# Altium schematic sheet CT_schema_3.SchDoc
size 221 x 258 mm
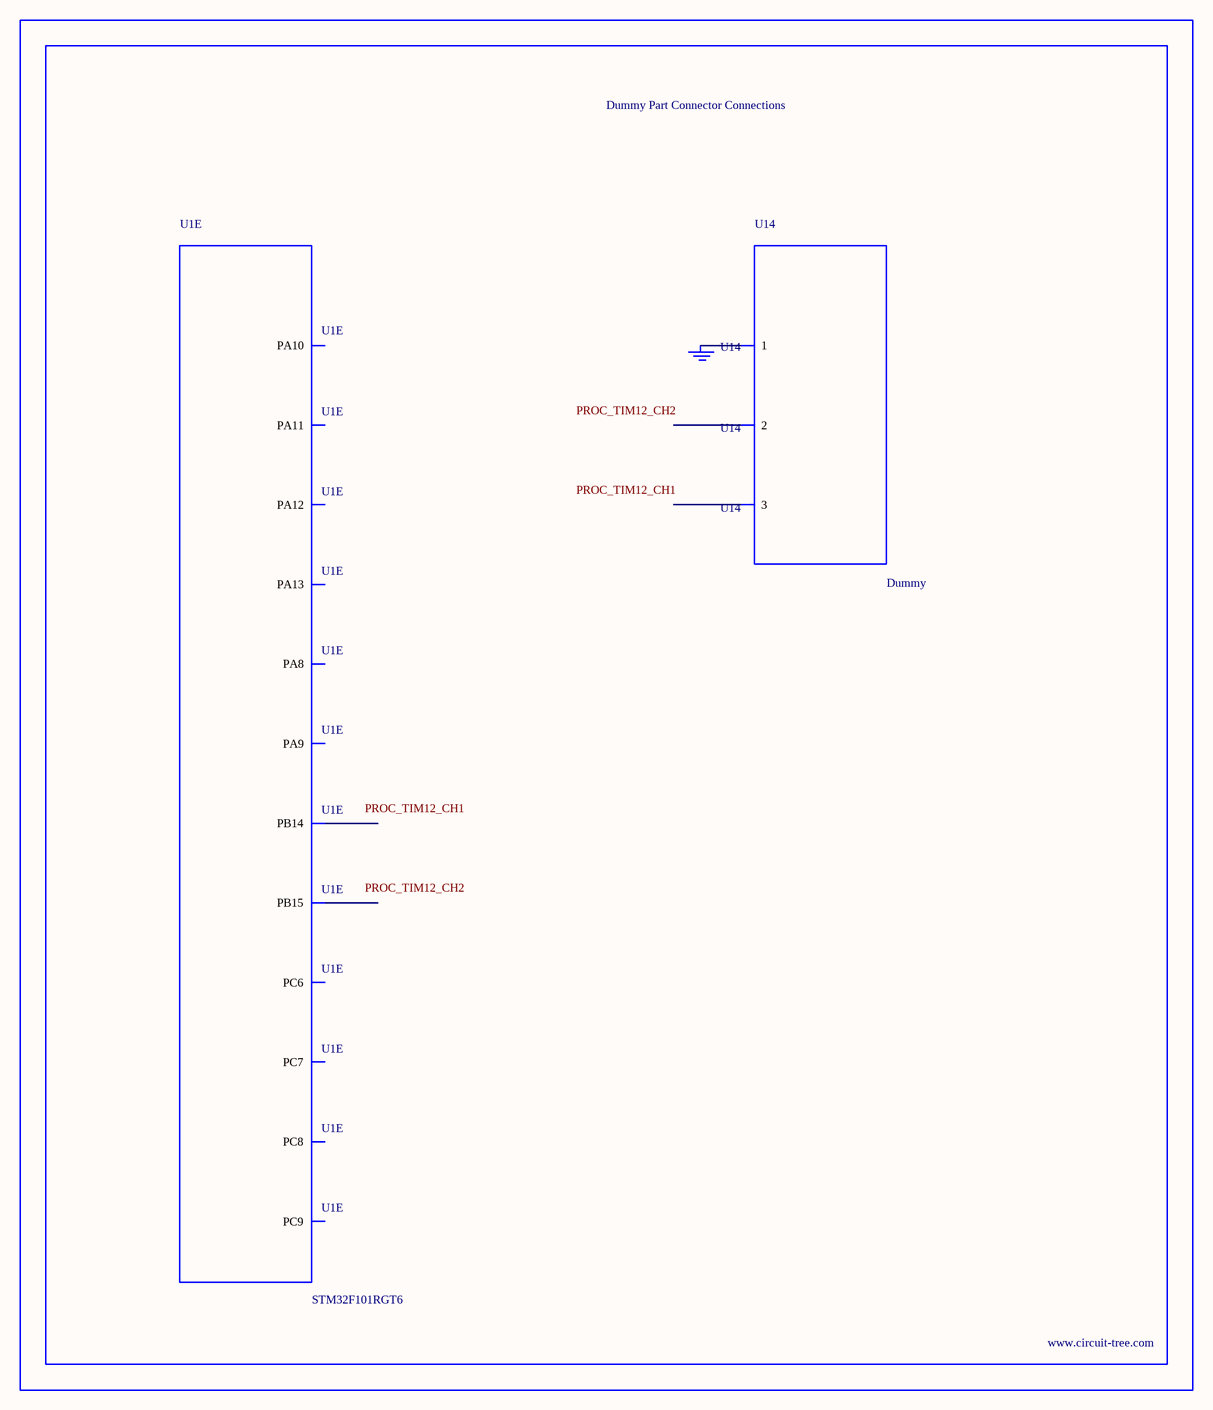
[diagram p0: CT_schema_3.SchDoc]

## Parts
BORDER2  (no value)
GND_INSTANCE_2_0  (no value)
U1  STM32F101RGT6  [LQFP64]  (part E of 5)
U14  Dummy  [DUMMY_PACKAGE_113]

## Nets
NetGND_INSTANCE_2_0_0: GND_INSTANCE_2_0.0(GND) U14.1

Not connected (* = marked no-connect by the designer): U1 35(PB14) 36(PB15) 37(PC6) 38(PC7) 39(PC8) 40(PC9) 41(PA8) 42(PA9) 43(PA10) 44(PA11) 45(PA12) 46(PA13); U14 2 3

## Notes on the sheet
- Labels drawn without touching a wire or pin: PROC_TIM12_CH1, PROC_TIM12_CH2

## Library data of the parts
BORDER2 = BORDER_PAGE2
GND_INSTANCE_2_0 = GND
